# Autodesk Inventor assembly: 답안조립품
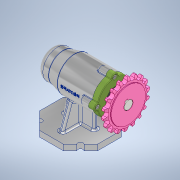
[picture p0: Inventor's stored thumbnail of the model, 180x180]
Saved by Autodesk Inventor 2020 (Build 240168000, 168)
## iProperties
Created: 2021-01
Part Number: 답안조립품
Document SubType Name: Assembly
Designer: USER
Author: USER
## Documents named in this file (12)
- C:\Users\USER\Desktop\710106V1037\답안조립품.iam
- C:\Users\USER\Desktop\710106V1037\본체.ipt
- C:\Users\USER\Desktop\710106V1037\베어링 6004.ipt
- C:\Users\USER\Desktop\710106V1037\베어링 51202.ipt
- C:\Users\USER\Desktop\710106V1037\볼트 M4.ipt
- C:\Users\USER\Desktop\710106V1037\어댑터슬리브.ipt
- C:\Users\USER\Desktop\710106V1037\오일 실.ipt
- C:\Users\USER\Desktop\710106V1037\축.ipt
- C:\Users\USER\Desktop\710106V1037\커버.ipt
- C:\Users\USER\Desktop\710106V1037\멈춤나사 M3.ipt
- C:\Users\USER\Desktop\710106V1037\스프로킷.ipt
- C:\Users\USER\Desktop\710106V1037\키 5 x 5 x 14.ipt
